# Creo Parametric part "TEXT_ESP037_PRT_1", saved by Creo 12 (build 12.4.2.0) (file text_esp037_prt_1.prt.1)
Units: Custom; MM, KILOGRAM, SECS

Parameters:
  PTC_WM_ITERATION = "0"
  PTC_WM_VERSION = "-.0"
  PTC_WM_LIFECYCLE_STATE = "In Work"
  PTC_WM_LIFECYCLE = "MO_CADDocument"
  PTC_WM_CREATED_BY = "Maximilian Roepper (Z0017RMS: MO)"
  PTC_WM_CREATED_ON = "18-Sep-26 11:36:42 AM"
  PTC_WM_MODIFIED_BY = "Maximilian Roepper (Z0017RMS: MO)"
  PTC_WM_MODIFIED_ON = "18-Sep-26 11:36:46 AM"
  PDMLINKNUMBER = "PDM000071454905"
  PTC_WM_NAME = "text_esp037_prt_1.prt"
  PTC_WM_NUMBER = "PDM000071454905"

Other parameters: WEIGHT, WEIGHT_FACTOR, WEIGHT_ADD, _MASS_TEMP, _DIFF_TEMP, MC_ERRORS, SUPPLIER

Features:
  1. coordinate system
  2. datum plane "PRT_YZ"
  3. datum plane "PRT_XY"
  4. datum plane "PRT_XZ"
  5. coordinate system
  6. datum axis
  7. datum axis
  8. datum axis
  9. coordinate system
  10. imported feature
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
Other named items: PRT, SIEMENS_MO, DRW_VIEW_ORG, PRT_X, PRT_Y, PRT_Z, CS0, ROUGH_GROB

Layers: 00_STD_CSYS-KSYS, 01_STD_PLANES-EBENEN, 02_STD_AXES-ACHSEN, 03_STD_CSYS-KSYS, 24_IMPORT_FEAT-IMPORT_KE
